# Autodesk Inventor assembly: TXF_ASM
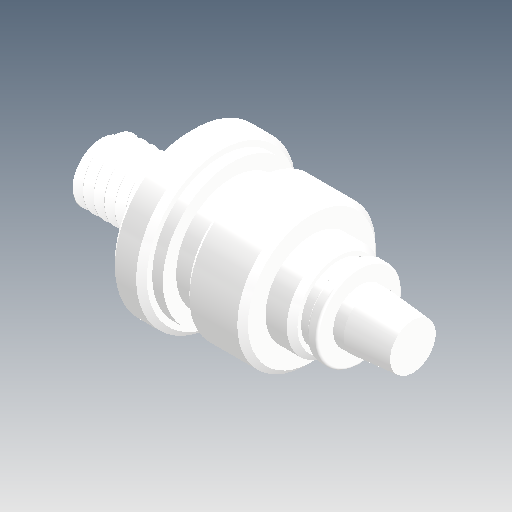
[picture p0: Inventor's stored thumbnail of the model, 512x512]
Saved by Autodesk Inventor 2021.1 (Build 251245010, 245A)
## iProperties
Created: 2021-05
Part Number: TXF_ASM
Document SubType Name: Assembly
Designer: user
Author: user
Revision Number: ÈÎºÎ
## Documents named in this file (3)
- D:\Vault_2016\Projekty\Clamptek\Hydraulic\CHLC\CHLC-25\Inventor\CHLC-MF25\TXF_ASM.iam
- D:\Vault_2016\Projekty\Clamptek\Hydraulic\CHLC\CHLC-25\Inventor\CHLC-MF25\TXF-02.ipt
- D:\Vault_2016\Projekty\Clamptek\Hydraulic\CHLC\CHLC-25\Inventor\CHLC-MF25\TSF-01.ipt
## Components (2 placed, 2 different names)
1. TXF-02_21
2. TSF-01_22
